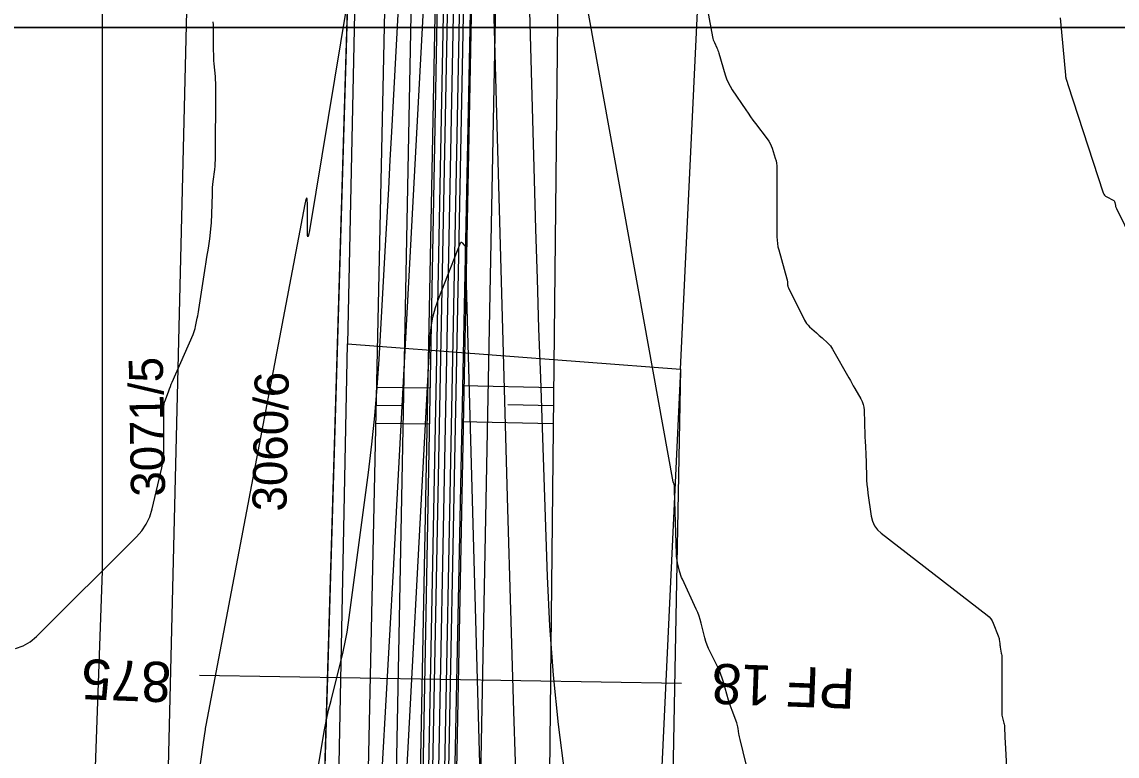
# Model space of a CAD drawing. Extents: x -534410 to -534262, y -1190162 to -1189584.
# Drawn here: x -534375.88 to -534348.61, y -1189707.6 to -1189689.33 of the extents above; entities that cross this region are included whole.
import ezdxf

# ---------------------------------------------------------------- set-up
doc = ezdxf.new("R2010")
doc.units = 0
for name, color, linetype in [('30', 7, 'Continuous'), ('31', 7, 'Continuous'), ('_linie', 7, 'Continuous'), ('_N_osa', 7, 'Continuous'), ('_N_tenká', 7, 'Continuous'), ('_N_tenká_velmi', 7, 'Continuous'), ('_N_text', 7, 'Continuous'), ('_rámeček', 7, 'Continuous'), ('_tenka', 7, 'Continuous'), ('_velmi_tenka', 7, 'Continuous'), ('Default', 7, 'Continuous'), ('Hranice parcel', 7, 'Continuous'), ('Parcelní čísla', 7, 'Continuous')]:
    doc.layers.add(name, color=color, linetype=linetype)

msp = doc.modelspace()

# ---------------------------------------------------------------- linework, layer by layer
at = {"layer": '30'}
for points in [[(-534365.702, -1189685.448), (-534366.553, -1189701.366), (-534366.64, -1189702.98), (-534366.729, -1189704.594), (-534366.819, -1189706.208), (-534366.911, -1189707.822), (-534367.302, -1189714.644)], [(-534357.772, -1189708.113), (-534358.002, -1189707.188), (-534358.01, -1189707.154), (-534358.018, -1189707.12), (-534358.024, -1189707.086), (-534358.029, -1189707.052), (-534358.049, -1189706.914), (-534358.055, -1189706.879), (-534358.062, -1189706.845), (-534358.072, -1189706.812), (-534358.083, -1189706.779), (-534358.201, -1189706.465), (-534358.224, -1189706.402), (-534358.246, -1189706.338), (-534358.266, -1189706.274), (-534358.286, -1189706.209), (-534358.413, -1189705.762), (-534358.443, -1189705.666), (-534358.477, -1189705.573), (-534358.515, -1189705.481), (-534358.558, -1189705.39), (-534358.748, -1189705.012), (-534358.788, -1189704.928), (-534358.822, -1189704.841), (-534358.852, -1189704.752), (-534358.878, -1189704.662), (-534358.968, -1189704.297), (-534358.993, -1189704.207), (-534359.022, -1189704.118), (-534359.055, -1189704.03), (-534359.093, -1189703.944), (-534359.437, -1189703.203), (-534359.458, -1189703.154), (-534359.477, -1189703.104), (-534359.494, -1189703.052), (-534359.507, -1189703), (-534359.558, -1189702.79), (-534359.569, -1189702.737), (-534359.578, -1189702.684), (-534359.583, -1189702.63), (-534359.586, -1189702.576), (-534359.631, -1189700.984), (-534359.632, -1189700.97), (-534359.632, -1189700.956), (-534359.633, -1189700.942), (-534359.633, -1189700.928), (-534359.637, -1189700.86), (-534359.638, -1189700.852), (-534359.639, -1189700.845), (-534359.641, -1189700.838), (-534359.644, -1189700.831), (-534359.657, -1189700.803), (-534359.66, -1189700.795), (-534359.663, -1189700.788), (-534359.665, -1189700.781), (-534359.666, -1189700.773), (-534362.25, -1189686.484)], [(-534362.885, -1189726.642), (-534362.961, -1189725.602), (-534363.011, -1189724.559), (-534363.467, -1189711.528), (-534363.552, -1189709.008), (-534363.634, -1189706.488), (-534363.71, -1189703.968), (-534363.782, -1189701.447), (-534364.144, -1189688.321)], [(-534367.79, -1189688.891), (-534368.719, -1189694.516), (-534368.742, -1189694.635), (-534368.758, -1189694.674), (-534368.768, -1189694.633), (-534368.772, -1189694.512), (-534368.773, -1189693.868), (-534368.778, -1189693.746), (-534368.789, -1189693.705), (-534368.808, -1189693.744), (-534368.834, -1189693.862), (-534371.3, -1189706.835), (-534371.307, -1189706.874), (-534371.314, -1189706.913), (-534371.32, -1189706.952), (-534371.326, -1189706.992), (-534371.366, -1189707.267), (-534371.561, -1189708.625)], [(-534350.03, -1189689.223), (-534349.902, -1189690.649), (-534349.9, -1189690.669), (-534349.896, -1189690.689), (-534349.892, -1189690.709), (-534349.887, -1189690.728), (-534349.863, -1189690.806), (-534349.857, -1189690.825), (-534349.851, -1189690.844), (-534349.845, -1189690.864), (-534349.839, -1189690.883), (-534348.957, -1189693.585), (-534348.943, -1189693.617), (-534348.924, -1189693.644), (-534348.9, -1189693.666), (-534348.87, -1189693.685), (-534348.714, -1189693.761), (-534348.698, -1189693.772), (-534348.685, -1189693.785), (-534348.676, -1189693.8), (-534348.67, -1189693.819), (-534348.656, -1189693.899), (-534348.652, -1189693.919), (-534348.646, -1189693.938), (-534348.639, -1189693.957), (-534348.631, -1189693.975), (-534348.24, -1189694.769)]]:
    msp.add_lwpolyline(points, dxfattribs=at)
at = {"layer": '31'}
for points in [[(-534371.1, -1189723.617), (-534368.388, -1189707.194), (-534368.345, -1189706.949), (-534368.297, -1189706.704), (-534368.243, -1189706.461), (-534368.184, -1189706.219), (-534367.938, -1189705.252), (-534367.88, -1189705.009), (-534367.829, -1189704.766), (-534367.785, -1189704.521), (-534367.749, -1189704.274), (-534367.255, -1189700.541), (-534367.169, -1189699.839), (-534367.096, -1189699.134), (-534367.035, -1189698.429), (-534366.988, -1189697.723), (-534366.826, -1189694.894), (-534366.786, -1189694.187), (-534366.746, -1189693.479), (-534366.708, -1189692.772), (-534366.669, -1189692.065), (-534366.397, -1189686.966)], [(-534363.277, -1189687.857), (-534363.128, -1189693.255), (-534363.093, -1189694.489), (-534363.055, -1189695.724), (-534363.015, -1189696.958), (-534362.973, -1189698.192), (-534362.801, -1189703.129), (-534362.742, -1189704.362), (-534362.651, -1189705.592), (-534362.529, -1189706.819), (-534362.375, -1189708.044)], [(-534358.81, -1189689.024), (-534358.684, -1189689.701), (-534358.677, -1189689.736), (-534358.667, -1189689.771), (-534358.655, -1189689.805), (-534358.641, -1189689.839), (-534358.581, -1189689.971), (-534358.566, -1189690.004), (-534358.553, -1189690.038), (-534358.541, -1189690.072), (-534358.53, -1189690.107), (-534358.372, -1189690.643), (-534358.338, -1189690.742), (-534358.298, -1189690.838), (-534358.25, -1189690.93), (-534358.195, -1189691.019), (-534357.859, -1189691.517), (-534357.8, -1189691.602), (-534357.741, -1189691.686), (-534357.68, -1189691.769), (-534357.618, -1189691.852), (-534357.323, -1189692.241), (-534357.286, -1189692.295), (-534357.254, -1189692.351), (-534357.226, -1189692.409), (-534357.204, -1189692.47), (-534357.124, -1189692.72), (-534357.106, -1189692.783), (-534357.094, -1189692.846), (-534357.086, -1189692.91), (-534357.084, -1189692.976), (-534357.084, -1189693.422), (-534357.084, -1189693.669), (-534357.084, -1189694.103), (-534357.084, -1189694.35), (-534357.084, -1189694.68), (-534357.081, -1189694.762), (-534357.072, -1189694.843), (-534357.058, -1189694.923), (-534357.039, -1189695.003), (-534356.836, -1189695.725), (-534356.831, -1189695.744), (-534356.827, -1189695.762), (-534356.824, -1189695.781), (-534356.822, -1189695.8), (-534356.816, -1189695.876), (-534356.814, -1189695.895), (-534356.81, -1189695.914), (-534356.804, -1189695.931), (-534356.796, -1189695.949), (-534356.399, -1189696.748), (-534356.373, -1189696.795), (-534356.343, -1189696.838), (-534356.309, -1189696.879), (-534356.271, -1189696.916), (-534356.101, -1189697.067), (-534356.03, -1189697.131), (-534355.958, -1189697.195), (-534355.815, -1189697.323), (-534355.78, -1189697.356), (-534355.749, -1189697.392), (-534355.721, -1189697.43), (-534355.696, -1189697.471), (-534355.292, -1189698.188), (-534355.255, -1189698.254), (-534355.218, -1189698.32), (-534355.181, -1189698.385), (-534355.144, -1189698.451), (-534354.995, -1189698.713), (-534354.962, -1189698.78), (-534354.937, -1189698.849), (-534354.922, -1189698.921), (-534354.915, -1189698.995), (-534354.894, -1189699.625), (-534354.893, -1189699.66), (-534354.892, -1189699.695), (-534354.89, -1189699.731), (-534354.888, -1189699.766), (-534354.879, -1189699.906), (-534354.877, -1189699.941), (-534354.875, -1189699.976), (-534354.873, -1189700.011), (-534354.872, -1189700.046), (-534354.854, -1189700.627), (-534354.85, -1189700.736), (-534354.842, -1189700.844), (-534354.831, -1189700.952), (-534354.816, -1189701.059), (-534354.733, -1189701.631), (-534354.703, -1189701.756), (-534354.652, -1189701.868), (-534354.579, -1189701.968), (-534354.485, -1189702.055), (-534351.845, -1189704.095), (-534351.798, -1189704.137), (-534351.757, -1189704.184), (-534351.723, -1189704.237), (-534351.696, -1189704.294), (-534351.571, -1189704.61), (-534351.563, -1189704.633), (-534351.556, -1189704.655), (-534351.551, -1189704.679), (-534351.548, -1189704.702), (-534351.536, -1189704.797), (-534351.533, -1189704.821), (-534351.53, -1189704.844), (-534351.526, -1189704.868), (-534351.522, -1189704.892), (-534351.497, -1189705.038), (-534351.492, -1189705.07), (-534351.488, -1189705.102), (-534351.486, -1189705.135), (-534351.486, -1189705.167), (-534351.486, -1189706.52), (-534351.484, -1189706.553), (-534351.481, -1189706.586), (-534351.476, -1189706.619), (-534351.468, -1189706.651), (-534351.434, -1189706.78), (-534351.426, -1189706.812), (-534351.421, -1189706.845), (-534351.417, -1189706.878), (-534351.415, -1189706.911), (-534351.409, -1189707.097), (-534351.408, -1189707.139), (-534351.406, -1189707.181), (-534351.404, -1189707.223), (-534351.402, -1189707.265), (-534351.34, -1189708.333)], [(-534376.037, -1189704.926), (-534375.85, -1189704.857), (-534375.678, -1189704.756), (-534375.52, -1189704.623), (-534373.029, -1189702.146), (-534372.894, -1189701.993), (-534372.784, -1189701.826), (-534372.699, -1189701.644), (-534372.638, -1189701.449), (-534372.396, -1189700.429), (-534372.376, -1189700.333), (-534372.361, -1189700.236), (-534372.353, -1189700.139), (-534372.35, -1189700.041), (-534372.35, -1189699.527), (-534372.35, -1189699.3), (-534372.35, -1189698.962), (-534372.348, -1189698.904), (-534372.34, -1189698.846), (-534372.327, -1189698.79), (-534372.309, -1189698.734), (-534372.226, -1189698.513), (-534372.205, -1189698.458), (-534372.184, -1189698.403), (-534372.161, -1189698.348), (-534372.138, -1189698.294), (-534371.62, -1189697.108), (-534371.6, -1189697.058), (-534371.583, -1189697.009), (-534371.568, -1189696.958), (-534371.556, -1189696.906), (-534371.514, -1189696.698), (-534371.503, -1189696.646), (-534371.494, -1189696.594), (-534371.485, -1189696.541), (-534371.476, -1189696.489), (-534371.308, -1189695.41), (-534371.299, -1189695.354), (-534371.29, -1189695.297), (-534371.281, -1189695.241), (-534371.272, -1189695.184), (-534371.234, -1189694.958), (-534371.225, -1189694.901), (-534371.217, -1189694.844), (-534371.209, -1189694.787), (-534371.203, -1189694.73), (-534371.17, -1189694.403), (-534371.163, -1189694.33), (-534371.158, -1189694.256), (-534371.154, -1189694.183), (-534371.151, -1189694.109), (-534371.139, -1189693.606), (-534371.136, -1189693.529), (-534371.131, -1189693.453), (-534371.125, -1189693.377), (-534371.117, -1189693.301), (-534371.08, -1189692.997), (-534371.072, -1189692.92), (-534371.066, -1189692.844), (-534371.063, -1189692.768), (-534371.062, -1189692.691), (-534371.063, -1189692.321), (-534371.063, -1189692.242), (-534371.062, -1189692.164), (-534371.061, -1189692.086), (-534371.059, -1189692.008), (-534371.052, -1189691.695), (-534371.05, -1189691.617), (-534371.049, -1189691.539), (-534371.049, -1189691.461), (-534371.049, -1189691.383), (-534371.049, -1189691.004), (-534371.05, -1189690.924), (-534371.053, -1189690.845), (-534371.057, -1189690.765), (-534371.064, -1189690.685), (-534371.092, -1189690.367), (-534371.098, -1189690.287), (-534371.102, -1189690.207), (-534371.105, -1189690.127), (-534371.106, -1189690.047), (-534371.106, -1189689.641), (-534371.107, -1189689.561), (-534371.109, -1189689.482), (-534371.113, -1189689.402), (-534371.118, -1189689.322)], [(-534366.657, -1189714.707), (-534366.581, -1189713.329), (-534366.452, -1189710.949), (-534365.716, -1189697.176), (-534365.693, -1189696.926), (-534365.65, -1189696.68), (-534365.587, -1189696.439), (-534365.504, -1189696.202), (-534364.963, -1189694.83), (-534364.955, -1189694.815), (-534364.945, -1189694.809), (-534364.934, -1189694.812), (-534364.922, -1189694.823), (-534364.868, -1189694.885), (-534364.857, -1189694.901), (-534364.848, -1189694.918), (-534364.843, -1189694.937), (-534364.841, -1189694.956), (-534364.38, -1189711.668), (-534364.3, -1189714.46), (-534364.216, -1189717.252), (-534364.126, -1189720.044), (-534364.031, -1189722.836), (-534363.168, -1189747.541)]]:
    msp.add_lwpolyline(points, dxfattribs=at)
at = {"layer": '_linie'}
for points in [[(-534366.12, -1189620.81), (-534364.52, -1189627.2), (-534365.69, -1189653.8), (-534366.76, -1189684.81), (-534368.14, -1189748.73), (-534368.38, -1189779.14), (-534368.65, -1189820.64), (-534368.59, -1189847.58), (-534367.2, -1189913.8)], [(-534363.12, -1189621.02), (-534362.79, -1189621.58), (-534361.82, -1189627.79), (-534363.46, -1189653.55), (-534365.47, -1189684.77), (-534366.65, -1189748.83), (-534366.75, -1189779.47), (-534366.9, -1189820.47), (-534366.95, -1189846.72), (-534366.338, -1189888.804), (-534363.85, -1189911.95), (-534357.07, -1189929.19), (-534352.334, -1189940.856)], [(-534359.03, -1189621.26), (-534359.41, -1189621.83), (-534360.84, -1189627.76), (-534362.92, -1189653.56), (-534364.64, -1189685), (-534365.94, -1189748.9), (-534366.02, -1189779.52), (-534366.03, -1189820.5), (-534366.48, -1189846.73), (-534365.511, -1189888.873), (-534362.72, -1189912.12), (-534356.62, -1189928.64), (-534351.589, -1189940.594)]]:
    msp.add_lwpolyline(points, dxfattribs=at)
at = {"layer": '_N_osa'}
msp.add_lwpolyline([(-534351.95, -1189940.722), (-534356.845, -1189928.915), (-534363.285, -1189912.035), (-534365.925, -1189888.838), (-534366.715, -1189846.725), (-534366.465, -1189820.485), (-534366.385, -1189779.495), (-534366.295, -1189748.865), (-534365.055, -1189684.885), (-534363.19, -1189653.555), (-534361.333, -1189627.822)], dxfattribs=at)
at = {"layer": '_N_tenká'}
for points in [[(-534352.92, -1189941.124), (-534357.821, -1189929.303), (-534364.313, -1189912.285), (-534366.973, -1189888.908), (-534367.765, -1189846.73), (-534367.515, -1189820.479), (-534367.435, -1189779.492), (-534367.345, -1189748.853), (-534366.104, -1189684.844), (-534364.238, -1189653.486), (-534362.424, -1189628.352), (-534361.782, -1189627.792)], [(-534350.98, -1189940.319), (-534355.869, -1189928.527), (-534362.257, -1189911.785), (-534364.876, -1189888.769), (-534365.665, -1189846.72), (-534365.415, -1189820.491), (-534365.335, -1189779.498), (-534365.245, -1189748.877), (-534364.006, -1189684.926), (-534362.142, -1189653.624), (-534360.329, -1189628.488), (-534360.884, -1189627.851)]]:
    msp.add_lwpolyline(points, dxfattribs=at)
at = {"layer": '_N_tenká_velmi'}
for points in [[(-534352.366, -1189940.894), (-534357.263, -1189929.081), (-534363.726, -1189912.142), (-534366.374, -1189888.868), (-534367.165, -1189846.727), (-534366.915, -1189820.482), (-534366.835, -1189779.494), (-534366.745, -1189748.86), (-534365.505, -1189684.867), (-534363.639, -1189653.525), (-534361.782, -1189627.792)], [(-534352.181, -1189940.817), (-534357.077, -1189929.007), (-534363.53, -1189912.095), (-534366.174, -1189888.855), (-534366.965, -1189846.726), (-534366.715, -1189820.484), (-534366.635, -1189779.494), (-534366.545, -1189748.862), (-534365.305, -1189684.875), (-534363.439, -1189653.539), (-534361.583, -1189627.805)], [(-534352.089, -1189940.779), (-534356.984, -1189928.97), (-534363.432, -1189912.071), (-534366.074, -1189888.848), (-534366.865, -1189846.726), (-534366.615, -1189820.484), (-534366.535, -1189779.495), (-534366.445, -1189748.863), (-534365.205, -1189684.879), (-534363.34, -1189653.545), (-534361.483, -1189627.812)], [(-534351.812, -1189940.664), (-534356.706, -1189928.86), (-534363.138, -1189911.999), (-534365.775, -1189888.828), (-534366.565, -1189846.724), (-534366.315, -1189820.486), (-534366.235, -1189779.495), (-534366.145, -1189748.867), (-534364.905, -1189684.891), (-534363.04, -1189653.565), (-534361.184, -1189627.831)], [(-534351.719, -1189940.626), (-534356.613, -1189928.823), (-534363.04, -1189911.975), (-534365.675, -1189888.822), (-534366.465, -1189846.724), (-534366.215, -1189820.486), (-534366.135, -1189779.496), (-534366.045, -1189748.868), (-534364.805, -1189684.895), (-534362.941, -1189653.571), (-534361.084, -1189627.838)], [(-534351.534, -1189940.549), (-534356.427, -1189928.749), (-534362.844, -1189911.928), (-534365.475, -1189888.808), (-534366.265, -1189846.723), (-534366.015, -1189820.488), (-534365.935, -1189779.496), (-534365.845, -1189748.87), (-534364.605, -1189684.903), (-534362.741, -1189653.585), (-534360.884, -1189627.851)]]:
    msp.add_lwpolyline(points, dxfattribs=at)
at = {"layer": '_N_text'}
msp.add_lwpolyline([(-534359.459, -1189705.793), (-534371.458, -1189705.599)], dxfattribs=at)
at = {"layer": '_rámeček'}
for points in [[(-534410.126, -1189584.47), (-534261.626, -1189584.47), (-534261.626, -1189689.47), (-534410.126, -1189689.47)], [(-534410.126, -1189689.47), (-534261.626, -1189689.47), (-534261.626, -1189794.47), (-534410.126, -1189794.47)]]:
    msp.add_lwpolyline(points, close=True, dxfattribs=at)
at = {"layer": '_tenka'}
for points in [[(-534349.13, -1189939.73), (-534354.63, -1189926.96), (-534362.03, -1189907.65), (-534364.521, -1189888.74), (-534364.47, -1189846.64), (-534364.29, -1189820.63), (-534364.22, -1189780.69), (-534363.18, -1189749.38), (-534362.5, -1189685.39), (-534360.27, -1189651.6), (-534357.03, -1189627.34), (-534354.77, -1189620.37)], [(-534366.12, -1189620.81), (-534364.52, -1189627.2), (-534365.69, -1189653.8), (-534366.76, -1189684.81), (-534368.14, -1189748.73), (-534368.38, -1189779.14), (-534368.65, -1189820.64), (-534368.59, -1189847.58), (-534367.2, -1189913.8)], [(-534366.12, -1189620.81), (-534364.52, -1189627.2), (-534365.69, -1189653.8), (-534366.76, -1189684.81), (-534368.14, -1189748.73), (-534368.38, -1189779.14), (-534368.65, -1189820.64), (-534368.59, -1189847.58), (-534367.2, -1189913.8)], [(-534363.12, -1189621.02), (-534362.79, -1189621.58), (-534361.82, -1189627.79), (-534363.46, -1189653.55), (-534365.47, -1189684.77), (-534366.65, -1189748.83), (-534366.75, -1189779.47), (-534366.9, -1189820.47), (-534366.95, -1189846.72), (-534366.338, -1189888.804), (-534363.85, -1189911.95), (-534357.07, -1189929.19), (-534352.334, -1189940.856)], [(-534363.12, -1189621.02), (-534362.79, -1189621.58), (-534361.82, -1189627.79), (-534363.46, -1189653.55), (-534365.47, -1189684.77), (-534366.65, -1189748.83), (-534366.75, -1189779.47), (-534366.9, -1189820.47), (-534366.95, -1189846.72), (-534366.338, -1189888.804), (-534363.85, -1189911.95), (-534357.07, -1189929.19), (-534352.334, -1189940.856)], [(-534359.03, -1189621.26), (-534359.41, -1189621.83), (-534360.84, -1189627.76), (-534362.92, -1189653.56), (-534364.64, -1189685), (-534365.94, -1189748.9), (-534366.02, -1189779.52), (-534366.03, -1189820.5), (-534366.48, -1189846.73), (-534365.511, -1189888.873), (-534362.72, -1189912.12), (-534356.62, -1189928.64), (-534351.589, -1189940.594)], [(-534359.03, -1189621.26), (-534359.41, -1189621.83), (-534360.84, -1189627.76), (-534362.92, -1189653.56), (-534364.64, -1189685), (-534365.94, -1189748.9), (-534366.02, -1189779.52), (-534366.03, -1189820.5), (-534366.48, -1189846.73), (-534365.511, -1189888.873), (-534362.72, -1189912.12), (-534356.62, -1189928.64), (-534351.589, -1189940.594)], [(-534368.65, -1189626.81), (-534368.65, -1189626.81), (-534367.31, -1189654.04), (-534367.67, -1189685.23), (-534369.56, -1189748.93), (-534369.48, -1189778.6), (-534369.45, -1189820.62), (-534369.45, -1189847.87), (-534371.206, -1189896.071), (-534372.39, -1189914.47)]]:
    msp.add_lwpolyline(points, dxfattribs=at)
at = {"layer": '_velmi_tenka'}
for p, q in [((-534367.058, -1189698.417), (-534365.724, -1189698.434)), ((-534362.633, -1189698.434), (-534364.911, -1189698.383)), ((-534367.063, -1189698.867), (-534366.397, -1189698.875)), ((-534362.643, -1189698.884), (-534363.782, -1189698.858)), ((-534367.069, -1189699.317), (-534365.736, -1189699.333)), ((-534362.654, -1189699.334), (-534364.932, -1189699.282))]:
    msp.add_line(p, q, dxfattribs=at)
at = {"layer": 'Default'}
msp.add_line((-534367.67, -1189685.23), (-534369.56, -1189748.93), dxfattribs=at)
msp.add_lwpolyline([(-534349.13, -1189939.73), (-534354.63, -1189926.96), (-534362.03, -1189907.65), (-534364.521, -1189888.74), (-534364.47, -1189846.64), (-534364.29, -1189820.63), (-534364.22, -1189780.69), (-534363.18, -1189749.38), (-534362.5, -1189685.39), (-534360.27, -1189651.6), (-534357.03, -1189627.34), (-534354.77, -1189620.37)], dxfattribs=at)
at = {"layer": 'Hranice parcel'}
for p, q in [((-534359.48, -1189697.97), (-534356.61, -1189636.93)), ((-534366.56, -1189638.19), (-534367.77, -1189697.34)), ((-534371.04, -1189658.4), (-534373.49, -1189759.21)), ((-534369.14, -1189764.19), (-534367.77, -1189697.34))]:
    msp.add_line(p, q, dxfattribs=at)
for points in [[(-534373.49, -1189759.21), (-534375.27, -1189742.09), (-534373.87, -1189702.99), (-534373.87, -1189662.03), (-534374.42, -1189646.7)], [(-534367.77, -1189697.34), (-534364.28, -1189697.61), (-534359.48, -1189697.97)], [(-534359.48, -1189697.97), (-534362.6, -1189764.35), (-534362.34, -1189901.56)], [(-534359.48, -1189697.97), (-534360.42, -1189747.8), (-534359.17, -1189788.69), (-534356.86, -1189843.2), (-534358.53, -1189915.98)]]:
    msp.add_lwpolyline(points, dxfattribs=at)

# ---------------------------------------------------------------- texts
at = {"layer": '_N_text'}
for s, rotation, p in [('875', 177.8451, (-534372.147, -1189705.27)), ('PF 18', 177.8926, (-534355.122, -1189705.43))]:
    msp.add_text(s, height=1, rotation=rotation, dxfattribs=at).set_placement(p)
at = {"layer": 'Parcelní čísla'}
for s, rotation, p in [('3071/5', 91, (-534372.312, -1189701.138)), ('3060/6', 89, (-534369.294, -1189701.52))]:
    msp.add_text(s, height=0.85, rotation=rotation, dxfattribs=at).set_placement(p)

doc.saveas('drawing.dxf')
